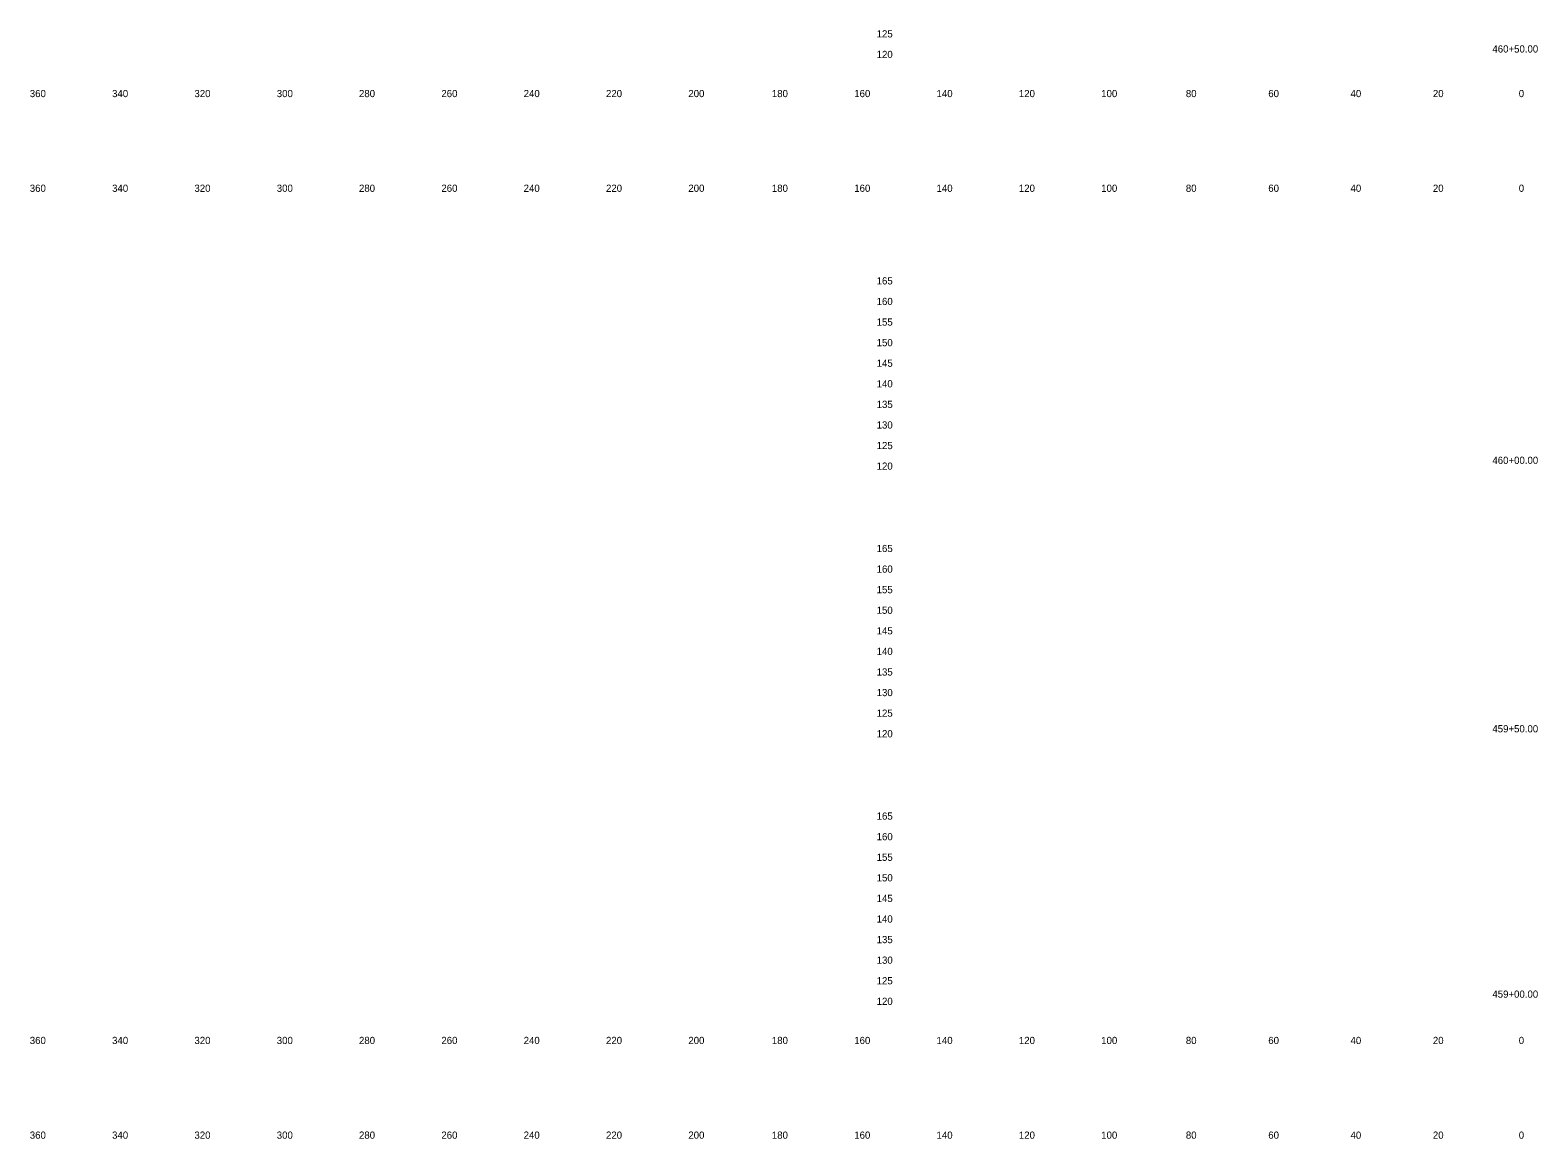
# Model space of a CAD drawing. Extents: x 21281 to 22024, y 6472 to 15198.
# Drawn here: x 21280.5 to 21646.7, y 7832.3 to 8101.6 of the extents above; entities that cross this region are included whole.
import ezdxf

# ---------------------------------------------------------------- set-up
doc = ezdxf.new("R2010")
doc.units = 0
for name, color, linetype in [('Draft_XS_Grid', 7, 'Continuous'), ('Draft_XS_Text', 7, 'Continuous'), ('SLOPE_STAKES_FILL', 7, 'Continuous')]:
    doc.layers.add(name, color=color, linetype=linetype)

msp = doc.modelspace()

# ---------------------------------------------------------------- texts
at = {"layer": 'Draft_XS_Grid'}
for s, p in [('  125  ', (21484.84, 8099.84)), ('  120  ', (21484.84, 8094.84)), ('  165  ', (21484.84, 8039.84)), ('  160  ', (21484.84, 8034.84)), ('  155  ', (21484.84, 8029.84)), ('  150  ', (21484.84, 8024.84)), ('  145  ', (21484.84, 8019.84)), ('  140  ', (21484.84, 8014.84)), ('  135  ', (21484.84, 8009.84)), ('  130  ', (21484.84, 8004.84)), ('  125  ', (21484.84, 7999.84)), ('  120  ', (21484.84, 7994.84)), ('  165  ', (21484.84, 7974.84)), ('  160  ', (21484.84, 7969.84)), ('  155  ', (21484.84, 7964.84)), ('  150  ', (21484.84, 7959.84)), ('  145  ', (21484.84, 7954.84)), ('  140  ', (21484.84, 7949.84)), ('  135  ', (21484.84, 7944.84)), ('  130  ', (21484.84, 7939.84)), ('  125  ', (21484.84, 7934.84)), ('  120  ', (21484.84, 7929.84)), ('  165  ', (21484.84, 7909.84)), ('  160  ', (21484.84, 7904.84)), ('  155  ', (21484.84, 7899.84)), ('  150  ', (21484.84, 7894.84)), ('  145  ', (21484.84, 7889.84)), ('  140  ', (21484.84, 7884.84)), ('  135  ', (21484.84, 7879.84)), ('  130  ', (21484.84, 7874.84)), ('  125  ', (21484.84, 7869.84)), ('  120  ', (21484.84, 7864.84))]:
    msp.add_text(s, height=1.75, dxfattribs=at).set_placement(p)
at = {"layer": 'Draft_XS_Text'}
for s, p in [('  360  ', (21279.14, 8085.34)), ('  340  ', (21299.13, 8085.34)), ('  320  ', (21319.13, 8085.34)), ('  300  ', (21339.13, 8085.34)), ('  280  ', (21359.1, 8085.34)), ('  260  ', (21379.11, 8085.34)), ('  240  ', (21399.1, 8085.34)), ('  220  ', (21419.1, 8085.34)), ('  200  ', (21439.1, 8085.34)), ('  180  ', (21459.39, 8085.34)), ('  160  ', (21479.4, 8085.34)), ('  140  ', (21499.39, 8085.34)), ('  120  ', (21519.39, 8085.34)), ('  100  ', (21539.39, 8085.34)), ('  80  ', (21559.95, 8085.34)), ('  60  ', (21579.97, 8085.34)), ('  40  ', (21599.95, 8085.34)), ('  20  ', (21619.95, 8085.34)), ('  0  ', (21640.81, 8085.34)), ('  0  ', (21640.81, 8085.34)), ('  360  ', (21279.14, 8062.34)), ('  340  ', (21299.13, 8062.34)), ('  320  ', (21319.13, 8062.34)), ('  300  ', (21339.13, 8062.34)), ('  280  ', (21359.1, 8062.34)), ('  260  ', (21379.11, 8062.34)), ('  240  ', (21399.1, 8062.34)), ('  220  ', (21419.1, 8062.34)), ('  200  ', (21439.1, 8062.34)), ('  180  ', (21459.39, 8062.34)), ('  160  ', (21479.4, 8062.34)), ('  140  ', (21499.39, 8062.34)), ('  120  ', (21519.39, 8062.34)), ('  100  ', (21539.39, 8062.34)), ('  80  ', (21559.95, 8062.34)), ('  60  ', (21579.97, 8062.34)), ('  40  ', (21599.95, 8062.34)), ('  20  ', (21619.95, 8062.34)), ('  0  ', (21640.81, 8062.34)), ('  0  ', (21640.81, 8062.34)), ('  360  ', (21279.14, 7855.34)), ('  340  ', (21299.13, 7855.34)), ('  320  ', (21319.13, 7855.34)), ('  300  ', (21339.13, 7855.34)), ('  280  ', (21359.1, 7855.34)), ('  260  ', (21379.11, 7855.34)), ('  240  ', (21399.1, 7855.34)), ('  220  ', (21419.1, 7855.34)), ('  200  ', (21439.1, 7855.34)), ('  180  ', (21459.39, 7855.34)), ('  160  ', (21479.4, 7855.34)), ('  140  ', (21499.39, 7855.34)), ('  120  ', (21519.39, 7855.34)), ('  100  ', (21539.39, 7855.34)), ('  80  ', (21559.95, 7855.34)), ('  60  ', (21579.97, 7855.34)), ('  40  ', (21599.95, 7855.34)), ('  20  ', (21619.95, 7855.34)), ('  0  ', (21640.81, 7855.34)), ('  0  ', (21640.81, 7855.34)), ('  360  ', (21279.14, 7832.34)), ('  340  ', (21299.13, 7832.34)), ('  320  ', (21319.13, 7832.34)), ('  300  ', (21339.13, 7832.34)), ('  280  ', (21359.1, 7832.34)), ('  260  ', (21379.11, 7832.34)), ('  240  ', (21399.1, 7832.34)), ('  220  ', (21419.1, 7832.34)), ('  200  ', (21439.1, 7832.34)), ('  180  ', (21459.39, 7832.34)), ('  160  ', (21479.4, 7832.34)), ('  140  ', (21499.39, 7832.34)), ('  120  ', (21519.39, 7832.34)), ('  100  ', (21539.39, 7832.34)), ('  80  ', (21559.95, 7832.34)), ('  60  ', (21579.97, 7832.34)), ('  40  ', (21599.95, 7832.34)), ('  20  ', (21619.95, 7832.34)), ('  0  ', (21640.81, 7832.34)), ('  0  ', (21640.81, 7832.34))]:
    msp.add_text(s, height=1.75, dxfattribs=at).set_placement(p)
at = {"layer": 'SLOPE_STAKES_FILL'}
for s, p in [('  460+50.00  ', (21634.41, 8096.17)), ('  460+00.00  ', (21634.41, 7996.25)), ('  459+50.00  ', (21634.4, 7931.05)), ('  459+00.00  ', (21634.4, 7866.59))]:
    msp.add_text(s, height=1.75, dxfattribs=at).set_placement(p)

doc.saveas('drawing.dxf')
